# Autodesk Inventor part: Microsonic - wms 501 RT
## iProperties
Shininess: 20.0
Length Units: 11269
Angle Units: 11279
Time Units: 11290
Mass Units: 11283
Length Display Precision: 2
Angle Display Precision: 2
Part Number: Microsonic - wms 501 RT
Material: Nylatron
Document SubType Name: Modellieren
Description: wms-501/RT
Checked By: Alves
Created: 2005-07
Designer: Tanck
Manufacturer: Standard
Standards Organization: Custom
Density: 0.0
Volumn: 0.0
Area: 0.0
PropertySet Name: Model Information
Control State: 0
Master: False
Checked Out: False
Last Check In By: Tanck
Last Check In Date: 2005-08-11
BESTELLNUMMER: wms-501/RT
ME: ST
Title: wms Sensoren
Author: Tanck
Comments: keine Bemerkung
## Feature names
1. Grundkörper [Extrusion]
2. Schallglocke links [Revolution]
3. Schallglocke rechts [Revolution]
4. Stirschräge [Extrusion]
5. Abrundung oben [Extrusion]
6. Grundkörper außen horizontal [Extrusion]
7. Grundkörper außen vertikal [Extrusion]
8. Rundung Auflagefläche [Fillet]
9. Rundung Außenkontur [Fillet]
10. Rundung Stirnfläche unten [Fillet]
11. Nicera - Wandler links [Extrusion]
12. Nicera - Wandler links innen [Extrusion]
13. Rundung Nicera - Wandler links [Fillet]
14. Gitterfläche [Extrusion]
15. Nicera - Wandler rechts [Mirror]
16. Steckeranschluß [Revolution]
17. Fase Steckeranschluß [Chamfer]
18. Rundung Gewindesockel [Fillet]
19. Fase Sechskant [Revolution]
20. Sechskant SW17 [Extrusion]
21. Kontaktpins [Extrusion]
22. Rundung Kontaktpins [Fillet]
23. Verdrehsicherung [Extrusion]
24. Rundung Verdrehsicherung [Fillet]
25. Auflage [Extrusion]
26. Duchgangsbohrungen [Hole]
27. Rundung Kontur oben links [Fillet]
28. Rundung Kontur oben rechts [Fillet]
29. Glocke vorn [Extrusion]
30. Rundung Stirschräge [Fillet]
31. Rundung Stirschrägenauflage [Fillet]
32. Rundung Stirschräge innen [Fillet]
33. Rundung Stirschräge innen oben links [Fillet]
34. Rundung Stirschräge innen oben rechts [Fillet]
35. Rundung Außenkontur vorn [Fillet]
